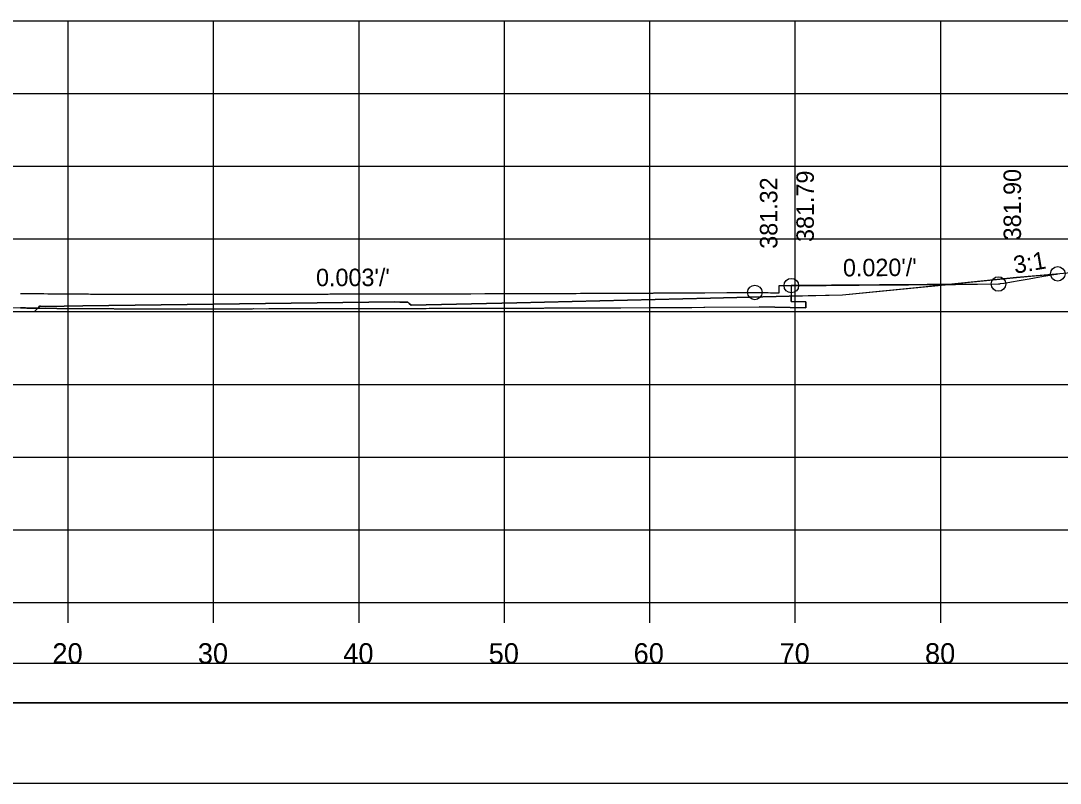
# Model space of a CAD drawing. Extents: x -37291014 to -37290680, y -936053 to -933067.
# Drawn here: x -37290826.4 to -37290754.9, y -934711.7 to -934659.3 of the extents above; entities that cross this region are included whole.
import ezdxf

# ---------------------------------------------------------------- set-up
doc = ezdxf.new("R2010")
doc.units = 0
for name, color, linetype in [('Default', 7, 'Continuous'), ('R_Alt Surface', 7, 'Continuous'), ('R_Axis', 7, 'Continuous'), ('R_Axis Annot', 7, 'Continuous'), ('R_Contours', 7, 'Continuous'), ('R_Exist Surface', 7, 'Continuous'), ('R_Fin Surface', 7, 'Continuous'), ('R_Grid', 7, 'Continuous'), ('R_No Plot', 7, 'Continuous'), ('R_Xsect Elev', 7, 'Continuous'), ('R_Xsect Slope', 7, 'Continuous')]:
    doc.layers.add(name, color=color, linetype=linetype)

msp = doc.modelspace()

# ---------------------------------------------------------------- linework, layer by layer
at = {"layer": 'Default'}
for points in [[(-37290992.311, -934706.202), (-37290693.892, -934706.202), (-37290693.892, -934703.496), (-37290992.311, -934703.496)], [(-37290992.311, -934711.724), (-37290693.892, -934711.724), (-37290693.892, -934706.202), (-37290992.311, -934706.202)]]:
    msp.add_lwpolyline(points, close=True, dxfattribs=at)
at = {"layer": 'R_Alt Surface'}
for points in [[(-37290773.377, -934677.506), (-37290773.377, -934678.599), (-37290772.367, -934678.619), (-37290772.377, -934679.036), (-37290775.582, -934678.972)], [(-37290826.373, -934679.04), (-37290826.283, -934679.042), (-37290826.078, -934679.044), (-37290826.028, -934679.045), (-37290825.955, -934679.046), (-37290825.658, -934679.05), (-37290825.6, -934679.051), (-37290825.591, -934679.051), (-37290825.259, -934679.055), (-37290825.215, -934679.055), (-37290825.062, -934679.057), (-37290824.832, -934679.059), (-37290824.797, -934679.06), (-37290824.773, -934679.06), (-37290824.491, -934679.063), (-37290824.373, -934679.064), (-37290824.346, -934679.064), (-37290823.883, -934679.068), (-37290823.872, -934679.069), (-37290823.858, -934679.069), (-37290823.358, -934679.073), (-37290823.331, -934679.073), (-37290823.203, -934679.074), (-37290822.796, -934679.077), (-37290822.762, -934679.077), (-37290822.479, -934679.079), (-37290822.26, -934679.08), (-37290822.196, -934679.081), (-37290822.147, -934679.081), (-37290821.695, -934679.084), (-37290821.556, -934679.084), (-37290821.483, -934679.085), (-37290820.872, -934679.088), (-37290820.848, -934679.088), (-37290820.766, -934679.088), (-37290820.144, -934679.091), (-37290819.992, -934679.091), (-37290819.931, -934679.092), (-37290819.367, -934679.094), (-37290819.2, -934679.094), (-37290819.157, -934679.094), (-37290818.939, -934679.095), (-37290818.54, -934679.096), (-37290817.864, -934679.098), (-37290817.659, -934679.098), (-37290816.722, -934679.1), (-37290816.7, -934679.1), (-37290815.725, -934679.101), (-37290815.557, -934679.101), (-37290815.414, -934679.1), (-37290815.413, -934679.1), (-37290815.296, -934679.1), (-37290815.24, -934679.1), (-37290815.223, -934679.1), (-37290815.047, -934679.099), (-37290815.016, -934679.099), (-37290814.946, -934679.099), (-37290814.714, -934679.099), (-37290814.603, -934679.099), (-37290814.555, -934679.099), (-37290814.439, -934679.098), (-37290814.323, -934679.098), (-37290814.184, -934679.097), (-37290814.125, -934679.097), (-37290814.072, -934679.097), (-37290813.328, -934679.098), (-37290813.063, -934679.097), (-37290813.056, -934679.097), (-37290812.949, -934679.096), (-37290812.934, -934679.096), (-37290812.779, -934679.096), (-37290812.714, -934679.095), (-37290812.153, -934679.096), (-37290811.918, -934679.095), (-37290811.886, -934679.095), (-37290811.801, -934679.094), (-37290811.601, -934679.094), (-37290811.432, -934679.093), (-37290810.941, -934679.093), (-37290810.882, -934679.093), (-37290810.777, -934679.093), (-37290810.725, -934679.093), (-37290810.563, -934679.092), (-37290810.429, -934679.092), (-37290810.359, -934679.091), (-37290809.495, -934679.092), (-37290809.311, -934679.091), (-37290809.206, -934679.091), (-37290808.971, -934679.09), (-37290808.915, -934679.09), (-37290808.697, -934679.09), (-37290808.616, -934679.089), (-37290808.29, -934679.088), (-37290808.228, -934679.088), (-37290808.218, -934679.088), (-37290807.103, -934679.088), (-37290806.768, -934679.087), (-37290806.723, -934679.086), (-37290806.574, -934679.086), (-37290806.351, -934679.085), (-37290806.279, -934679.085), (-37290806.269, -934679.085), (-37290806.236, -934679.085), (-37290806.213, -934679.085), (-37290805.95, -934679.084), (-37290805.221, -934679.084), (-37290805.117, -934679.083), (-37290805.092, -934679.083), (-37290804.69, -934679.082), (-37290804.364, -934679.082), (-37290804.355, -934679.082), (-37290804.343, -934679.082), (-37290803.985, -934679.081), (-37290803.58, -934679.08), (-37290803.524, -934679.08), (-37290803.503, -934679.08), (-37290803.402, -934679.079), (-37290802.641, -934679.079), (-37290802.338, -934679.078), (-37290802.312, -934679.078), (-37290802.107, -934679.077), (-37290801.951, -934679.076), (-37290801.18, -934679.075), (-37290801.136, -934679.075), (-37290801.103, -934679.075), (-37290800.802, -934679.074), (-37290800.374, -934679.074), (-37290800.284, -934679.073), (-37290800.238, -934679.073), (-37290799.858, -934679.072), (-37290798.898, -934679.07), (-37290798.884, -934679.07), (-37290798.837, -934679.07), (-37290798.484, -934679.069), (-37290798.277, -934679.068), (-37290798.214, -934679.068), (-37290798.132, -934679.068), (-37290798.099, -934679.068), (-37290797.798, -934679.067), (-37290796.535, -934679.064), (-37290796.454, -934679.064), (-37290796.433, -934679.064), (-37290796.328, -934679.064), (-37290796.139, -934679.063), (-37290795.797, -934679.062), (-37290795.493, -934679.061), (-37290795.403, -934679.061), (-37290794.448, -934679.059), (-37290794.07, -934679.057), (-37290794.061, -934679.057), (-37290793.272, -934679.055), (-37290792.915, -934679.054), (-37290792.374, -934679.052), (-37290792.293, -934679.052), (-37290792.276, -934679.052), (-37290791.775, -934679.05), (-37290791.525, -934679.049), (-37290791.431, -934679.049), (-37290791.247, -934679.049), (-37290790.557, -934679.046), (-37290790.404, -934679.046), (-37290790.323, -934679.045), (-37290790.286, -934679.045), (-37290790.022, -934679.044), (-37290789.956, -934679.044), (-37290788.166, -934679.038), (-37290787.878, -934679.037), (-37290787.86, -934679.037), (-37290787.857, -934679.037), (-37290787.004, -934679.033), (-37290786.833, -934679.032), (-37290786.756, -934679.032), (-37290786.476, -934679.031), (-37290786.396, -934679.031), (-37290786.384, -934679.031), (-37290785.5, -934679.027), (-37290785.346, -934679.026), (-37290785.191, -934679.026), (-37290785.106, -934679.025), (-37290783.063, -934679.015), (-37290782.918, -934679.015), (-37290782.887, -934679.015), (-37290782.878, -934679.015), (-37290782.824, -934679.014), (-37290782.813, -934679.014), (-37290782.629, -934679.014), (-37290780.409, -934679.001), (-37290780.377, -934679.001), (-37290780.287, -934679.001), (-37290780.214, -934679.001), (-37290779.401, -934678.996), (-37290779.361, -934678.996), (-37290779.324, -934678.996), (-37290779.317, -934678.996), (-37290775.582, -934678.972)]]:
    msp.add_lwpolyline(points, dxfattribs=at)
at = {"layer": 'R_Axis'}
for p, q in [((-37290993.102, -934699.296), (-37290693.102, -934699.296)), ((-37290823.102, -934700.696), (-37290823.102, -934699.296)), ((-37290813.102, -934700.696), (-37290813.102, -934699.296)), ((-37290803.102, -934700.696), (-37290803.102, -934699.296)), ((-37290793.102, -934700.696), (-37290793.102, -934699.296)), ((-37290783.102, -934700.696), (-37290783.102, -934699.296)), ((-37290773.102, -934700.696), (-37290773.102, -934699.296)), ((-37290763.102, -934700.696), (-37290763.102, -934699.296))]:
    msp.add_line(p, q, dxfattribs=at)
at = {"layer": 'R_Contours'}
msp.add_line((-37290773.377, -934677.506), (-37290773.377, -934678.218), dxfattribs=at)
for points in [[(-37290755.183, -934676.709), (-37290757.888, -934676.958), (-37290762.564, -934677.424)], [(-37290762.564, -934677.424), (-37290762.364, -934677.422), (-37290762.075, -934677.42), (-37290761.796, -934677.418), (-37290760.578, -934677.407), (-37290759.131, -934677.394), (-37290759.035, -934677.378), (-37290758.994, -934677.37), (-37290758.769, -934677.331), (-37290758.745, -934677.327), (-37290758.095, -934677.215), (-37290757.854, -934677.173), (-37290757.018, -934677.03), (-37290756.043, -934676.864), (-37290755.88, -934676.836), (-37290755.183, -934676.718)], [(-37290755.183, -934676.718), (-37290755.183, -934676.709)], [(-37290773.377, -934678.218), (-37290769.863, -934678.151), (-37290762.564, -934677.424)], [(-37290762.564, -934677.424), (-37290763.36, -934677.431), (-37290764.024, -934677.436), (-37290765.308, -934677.446), (-37290765.785, -934677.45), (-37290766.202, -934677.454), (-37290766.23, -934677.454), (-37290766.258, -934677.454), (-37290767.302, -934677.462), (-37290768.716, -934677.473), (-37290768.987, -934677.475), (-37290769.108, -934677.476), (-37290770.606, -934677.487), (-37290770.972, -934677.489), (-37290771.146, -934677.49), (-37290772.081, -934677.497), (-37290772.308, -934677.499), (-37290772.327, -934677.499), (-37290773.377, -934677.506)], [(-37290773.377, -934678.218), (-37290773.528, -934678.221), (-37290778.937, -934678.366), (-37290792.257, -934678.695), (-37290799.508, -934678.849), (-37290799.643, -934678.73), (-37290799.749, -934678.645), (-37290800.07, -934678.644), (-37290800.294, -934678.643), (-37290800.668, -934678.627), (-37290809.532, -934678.742), (-37290822.086, -934678.905), (-37290824.665, -934678.932), (-37290825.008, -934678.927), (-37290825.065, -934678.928), (-37290825.113, -934678.982), (-37290825.186, -934679.056)], [(-37290775.582, -934678.972), (-37290772.377, -934679.036), (-37290772.367, -934678.619), (-37290773.377, -934678.599), (-37290773.377, -934678.218)], [(-37290832.102, -934679.295), (-37290831.45, -934679.298), (-37290825.393, -934679.265), (-37290825.186, -934679.056)], [(-37290825.186, -934679.056), (-37290825.215, -934679.055), (-37290825.259, -934679.055), (-37290825.6, -934679.051), (-37290825.658, -934679.05), (-37290825.955, -934679.046), (-37290826.028, -934679.045), (-37290826.078, -934679.044), (-37290826.283, -934679.042), (-37290826.373, -934679.04), (-37290826.389, -934679.04), (-37290829.102, -934679.105)], [(-37290825.186, -934679.056), (-37290825.062, -934679.057), (-37290824.832, -934679.059), (-37290824.797, -934679.06), (-37290824.773, -934679.06), (-37290824.491, -934679.063), (-37290824.373, -934679.064), (-37290824.346, -934679.064), (-37290823.883, -934679.068), (-37290823.872, -934679.069), (-37290823.858, -934679.069), (-37290823.358, -934679.073), (-37290823.331, -934679.073), (-37290823.203, -934679.074), (-37290822.796, -934679.077), (-37290822.762, -934679.077), (-37290822.479, -934679.079), (-37290822.26, -934679.08), (-37290822.196, -934679.081), (-37290822.147, -934679.081), (-37290821.695, -934679.084), (-37290821.556, -934679.084), (-37290821.483, -934679.085), (-37290820.872, -934679.088), (-37290820.848, -934679.088), (-37290820.766, -934679.088), (-37290820.144, -934679.091), (-37290819.992, -934679.091), (-37290819.931, -934679.092), (-37290819.367, -934679.094), (-37290819.2, -934679.094), (-37290819.157, -934679.094), (-37290818.939, -934679.095), (-37290818.54, -934679.096), (-37290817.864, -934679.098), (-37290817.659, -934679.098), (-37290816.722, -934679.1), (-37290816.7, -934679.1), (-37290815.725, -934679.101), (-37290815.557, -934679.101), (-37290815.414, -934679.1), (-37290815.296, -934679.1), (-37290815.24, -934679.1), (-37290815.223, -934679.1), (-37290815.047, -934679.099), (-37290815.016, -934679.099), (-37290814.946, -934679.099), (-37290814.714, -934679.099), (-37290814.603, -934679.099), (-37290814.555, -934679.099), (-37290814.439, -934679.098), (-37290814.323, -934679.098), (-37290814.184, -934679.097), (-37290814.125, -934679.097), (-37290814.072, -934679.097), (-37290813.328, -934679.098), (-37290813.063, -934679.097), (-37290812.949, -934679.096), (-37290812.934, -934679.096), (-37290812.779, -934679.096), (-37290812.714, -934679.095), (-37290812.153, -934679.096), (-37290811.918, -934679.095), (-37290811.886, -934679.095), (-37290811.801, -934679.094), (-37290811.601, -934679.094), (-37290811.432, -934679.093), (-37290810.941, -934679.093), (-37290810.882, -934679.093), (-37290810.777, -934679.093), (-37290810.725, -934679.093), (-37290810.563, -934679.092), (-37290810.429, -934679.092), (-37290810.359, -934679.091), (-37290809.495, -934679.092), (-37290809.311, -934679.091), (-37290809.206, -934679.091), (-37290808.971, -934679.09), (-37290808.915, -934679.09), (-37290808.697, -934679.09), (-37290808.616, -934679.089), (-37290808.29, -934679.088), (-37290808.228, -934679.088), (-37290807.103, -934679.088), (-37290806.768, -934679.087), (-37290806.723, -934679.086), (-37290806.574, -934679.086), (-37290806.351, -934679.085), (-37290806.279, -934679.085), (-37290806.236, -934679.085), (-37290806.213, -934679.085), (-37290805.95, -934679.084), (-37290805.221, -934679.084), (-37290805.117, -934679.083), (-37290805.092, -934679.083), (-37290804.69, -934679.082), (-37290804.364, -934679.082), (-37290804.343, -934679.082), (-37290803.985, -934679.081), (-37290803.58, -934679.08), (-37290803.524, -934679.08), (-37290803.503, -934679.08), (-37290803.402, -934679.079), (-37290802.641, -934679.079), (-37290802.338, -934679.078), (-37290802.312, -934679.078), (-37290802.107, -934679.077), (-37290801.951, -934679.076), (-37290801.18, -934679.075), (-37290801.136, -934679.075), (-37290801.103, -934679.075), (-37290800.802, -934679.074), (-37290800.374, -934679.074), (-37290800.284, -934679.073), (-37290800.238, -934679.073), (-37290799.858, -934679.072), (-37290798.898, -934679.07), (-37290798.884, -934679.07), (-37290798.837, -934679.07), (-37290798.484, -934679.069), (-37290798.277, -934679.068), (-37290798.214, -934679.068), (-37290798.132, -934679.068), (-37290798.099, -934679.068), (-37290797.798, -934679.067), (-37290796.535, -934679.064), (-37290796.454, -934679.064), (-37290796.433, -934679.064), (-37290796.328, -934679.064), (-37290796.139, -934679.063), (-37290795.797, -934679.062), (-37290795.493, -934679.061), (-37290795.403, -934679.061), (-37290794.448, -934679.059), (-37290794.07, -934679.057), (-37290793.272, -934679.055), (-37290792.915, -934679.054), (-37290792.374, -934679.052), (-37290792.293, -934679.052), (-37290792.276, -934679.052), (-37290791.775, -934679.05), (-37290791.525, -934679.049), (-37290791.431, -934679.049), (-37290791.247, -934679.049), (-37290790.557, -934679.046), (-37290790.404, -934679.046), (-37290790.323, -934679.045), (-37290790.286, -934679.045), (-37290790.022, -934679.044), (-37290789.956, -934679.044), (-37290788.166, -934679.038), (-37290787.878, -934679.037), (-37290787.86, -934679.037), (-37290787.004, -934679.033), (-37290786.833, -934679.032), (-37290786.756, -934679.032), (-37290786.476, -934679.031), (-37290786.396, -934679.031), (-37290786.384, -934679.031), (-37290785.5, -934679.027), (-37290785.346, -934679.026), (-37290785.191, -934679.026), (-37290785.106, -934679.025), (-37290783.063, -934679.015), (-37290782.918, -934679.015), (-37290782.887, -934679.015), (-37290782.824, -934679.014), (-37290782.813, -934679.014), (-37290782.629, -934679.014), (-37290780.409, -934679.001), (-37290780.377, -934679.001), (-37290780.287, -934679.001), (-37290780.214, -934679.001), (-37290779.401, -934678.996), (-37290779.361, -934678.996), (-37290779.324, -934678.996), (-37290775.582, -934678.972)]]:
    msp.add_lwpolyline(points, dxfattribs=at)
at = {"layer": 'R_Exist Surface'}
msp.add_lwpolyline([(-37290831.45, -934679.298), (-37290825.393, -934679.265), (-37290825.113, -934678.982), (-37290825.065, -934678.928), (-37290825.008, -934678.927), (-37290824.665, -934678.932), (-37290822.086, -934678.905), (-37290809.532, -934678.742), (-37290800.668, -934678.627), (-37290800.294, -934678.643), (-37290800.07, -934678.644), (-37290799.749, -934678.645), (-37290799.643, -934678.73), (-37290799.508, -934678.849), (-37290792.257, -934678.695), (-37290778.937, -934678.366), (-37290773.528, -934678.221), (-37290769.863, -934678.151), (-37290757.888, -934676.958), (-37290746.73, -934675.928)], dxfattribs=at)
at = {"layer": 'R_Fin Surface'}
msp.add_lwpolyline([(-37290826.373, -934678.04), (-37290826.284, -934678.041), (-37290826.079, -934678.044), (-37290826.029, -934678.045), (-37290825.956, -934678.046), (-37290825.658, -934678.05), (-37290825.6, -934678.051), (-37290825.591, -934678.051), (-37290825.26, -934678.055), (-37290825.215, -934678.055), (-37290825.063, -934678.057), (-37290824.832, -934678.059), (-37290824.798, -934678.06), (-37290824.774, -934678.06), (-37290824.491, -934678.063), (-37290824.374, -934678.064), (-37290824.347, -934678.064), (-37290823.883, -934678.068), (-37290823.873, -934678.068), (-37290823.859, -934678.069), (-37290823.358, -934678.073), (-37290823.332, -934678.073), (-37290823.203, -934678.074), (-37290822.797, -934678.077), (-37290822.762, -934678.077), (-37290822.479, -934678.079), (-37290822.26, -934678.08), (-37290822.197, -934678.081), (-37290822.147, -934678.081), (-37290821.696, -934678.083), (-37290821.556, -934678.084), (-37290821.483, -934678.085), (-37290820.873, -934678.088), (-37290820.849, -934678.088), (-37290820.767, -934678.088), (-37290820.144, -934678.091), (-37290819.993, -934678.091), (-37290819.932, -934678.092), (-37290819.368, -934678.094), (-37290819.201, -934678.094), (-37290819.158, -934678.094), (-37290818.939, -934678.095), (-37290818.541, -934678.096), (-37290817.865, -934678.098), (-37290817.66, -934678.098), (-37290816.722, -934678.1), (-37290816.701, -934678.1), (-37290815.725, -934678.101), (-37290815.558, -934678.101), (-37290815.415, -934678.1), (-37290815.413, -934678.1), (-37290815.297, -934678.1), (-37290815.241, -934678.1), (-37290815.224, -934678.1), (-37290815.048, -934678.099), (-37290815.017, -934678.099), (-37290814.947, -934678.099), (-37290814.715, -934678.099), (-37290814.604, -934678.098), (-37290814.555, -934678.098), (-37290814.44, -934678.098), (-37290814.324, -934678.098), (-37290814.185, -934678.097), (-37290814.126, -934678.097), (-37290814.073, -934678.097), (-37290813.329, -934678.097), (-37290813.064, -934678.097), (-37290813.056, -934678.096), (-37290812.95, -934678.096), (-37290812.934, -934678.096), (-37290812.78, -934678.095), (-37290812.715, -934678.095), (-37290812.153, -934678.096), (-37290811.919, -934678.095), (-37290811.887, -934678.095), (-37290811.801, -934678.094), (-37290811.602, -934678.094), (-37290811.433, -934678.093), (-37290810.941, -934678.093), (-37290810.882, -934678.093), (-37290810.778, -934678.093), (-37290810.726, -934678.093), (-37290810.564, -934678.092), (-37290810.429, -934678.092), (-37290810.36, -934678.091), (-37290809.495, -934678.092), (-37290809.312, -934678.091), (-37290809.207, -934678.091), (-37290808.972, -934678.09), (-37290808.916, -934678.089), (-37290808.698, -934678.09), (-37290808.616, -934678.089), (-37290808.291, -934678.088), (-37290808.229, -934678.088), (-37290808.219, -934678.088), (-37290807.103, -934678.088), (-37290806.768, -934678.087), (-37290806.724, -934678.086), (-37290806.575, -934678.086), (-37290806.352, -934678.085), (-37290806.279, -934678.085), (-37290806.27, -934678.085), (-37290806.237, -934678.085), (-37290806.214, -934678.085), (-37290805.95, -934678.084), (-37290805.222, -934678.084), (-37290805.117, -934678.083), (-37290805.093, -934678.083), (-37290804.69, -934678.082), (-37290804.364, -934678.082), (-37290804.355, -934678.081), (-37290804.344, -934678.081), (-37290803.986, -934678.081), (-37290803.58, -934678.08), (-37290803.525, -934678.08), (-37290803.504, -934678.08), (-37290803.403, -934678.079), (-37290802.642, -934678.079), (-37290802.338, -934678.078), (-37290802.313, -934678.077), (-37290802.108, -934678.077), (-37290801.952, -934678.076), (-37290801.18, -934678.075), (-37290801.137, -934678.075), (-37290801.103, -934678.075), (-37290800.802, -934678.074), (-37290800.374, -934678.073), (-37290800.285, -934678.073), (-37290800.239, -934678.073), (-37290799.859, -934678.072), (-37290798.899, -934678.07), (-37290798.885, -934678.07), (-37290798.837, -934678.07), (-37290798.484, -934678.069), (-37290798.278, -934678.068), (-37290798.215, -934678.068), (-37290798.132, -934678.068), (-37290798.099, -934678.068), (-37290797.799, -934678.067), (-37290796.536, -934678.064), (-37290796.454, -934678.064), (-37290796.433, -934678.064), (-37290796.328, -934678.064), (-37290796.14, -934678.063), (-37290795.798, -934678.062), (-37290795.494, -934678.061), (-37290795.404, -934678.061), (-37290794.449, -934678.058), (-37290794.07, -934678.057), (-37290794.062, -934678.057), (-37290793.272, -934678.055), (-37290792.916, -934678.054), (-37290792.374, -934678.052), (-37290792.293, -934678.052), (-37290792.276, -934678.052), (-37290791.776, -934678.05), (-37290791.526, -934678.049), (-37290791.432, -934678.049), (-37290791.247, -934678.048), (-37290790.558, -934678.046), (-37290790.405, -934678.046), (-37290790.324, -934678.045), (-37290790.286, -934678.045), (-37290790.023, -934678.044), (-37290789.957, -934678.044), (-37290788.166, -934678.038), (-37290787.879, -934678.037), (-37290787.86, -934678.036), (-37290787.858, -934678.036), (-37290787.005, -934678.033), (-37290786.833, -934678.032), (-37290786.757, -934678.032), (-37290786.477, -934678.031), (-37290786.397, -934678.031), (-37290786.384, -934678.031), (-37290785.5, -934678.027), (-37290785.346, -934678.026), (-37290785.191, -934678.026), (-37290785.106, -934678.025), (-37290783.064, -934678.015), (-37290782.919, -934678.015), (-37290782.888, -934678.015), (-37290782.878, -934678.015), (-37290782.825, -934678.014), (-37290782.814, -934678.014), (-37290782.629, -934678.014), (-37290780.41, -934678.001), (-37290780.377, -934678.001), (-37290780.287, -934678.001), (-37290780.214, -934678.001), (-37290779.401, -934677.996), (-37290779.361, -934677.996), (-37290779.325, -934677.996), (-37290779.318, -934677.996), (-37290777.804, -934677.986), (-37290777.776, -934677.986), (-37290777.773, -934677.986), (-37290777.771, -934677.986), (-37290777.719, -934677.986), (-37290776.119, -934677.975), (-37290776.116, -934677.975), (-37290775.885, -934677.973), (-37290775.127, -934677.986), (-37290774.979, -934677.989), (-37290774.802, -934677.992), (-37290774.22, -934678.002), (-37290774.219, -934677.885), (-37290774.218, -934677.502), (-37290773.736, -934677.504), (-37290773.377, -934677.506), (-37290772.327, -934677.499), (-37290772.308, -934677.499), (-37290772.081, -934677.497), (-37290771.146, -934677.49), (-37290770.972, -934677.489), (-37290770.606, -934677.487), (-37290769.108, -934677.476), (-37290768.987, -934677.475), (-37290768.716, -934677.473), (-37290767.302, -934677.462), (-37290766.258, -934677.454), (-37290766.23, -934677.454), (-37290766.202, -934677.454), (-37290765.785, -934677.45), (-37290765.308, -934677.446), (-37290764.024, -934677.436), (-37290763.36, -934677.431), (-37290762.364, -934677.422), (-37290762.075, -934677.42), (-37290761.796, -934677.418), (-37290760.578, -934677.407), (-37290759.131, -934677.394), (-37290759.035, -934677.378), (-37290758.994, -934677.37), (-37290758.769, -934677.331), (-37290758.745, -934677.327), (-37290758.095, -934677.215), (-37290757.854, -934677.173), (-37290757.018, -934677.03), (-37290756.043, -934676.864), (-37290755.88, -934676.836), (-37290755.183, -934676.718), (-37290755.143, -934676.712), (-37290755.052, -934676.696)], dxfattribs=at)
at = {"layer": 'R_Grid'}
for p, q in [((-37290993.102, -934659.296), (-37290693.102, -934659.296)), ((-37290823.102, -934699.296), (-37290823.102, -934659.296)), ((-37290813.102, -934699.296), (-37290813.102, -934659.296)), ((-37290803.102, -934699.296), (-37290803.102, -934659.296)), ((-37290793.102, -934699.296), (-37290793.102, -934659.296)), ((-37290783.102, -934699.296), (-37290783.102, -934659.296)), ((-37290773.102, -934699.296), (-37290773.102, -934659.296)), ((-37290763.102, -934699.296), (-37290763.102, -934659.296)), ((-37290993.102, -934664.296), (-37290693.102, -934664.296)), ((-37290993.102, -934669.296), (-37290693.102, -934669.296)), ((-37290993.102, -934674.296), (-37290693.102, -934674.296)), ((-37290993.102, -934679.296), (-37290693.102, -934679.296)), ((-37290993.102, -934684.296), (-37290693.102, -934684.296)), ((-37290993.102, -934689.296), (-37290693.102, -934689.296)), ((-37290993.102, -934694.296), (-37290693.102, -934694.296)), ((-37290993.102, -934699.296), (-37290693.102, -934699.296))]:
    msp.add_line(p, q, dxfattribs=at)
at = {"layer": 'R_No Plot'}
for centre in [(-37290755.052, -934676.696), (-37290773.377, -934677.506), (-37290759.131, -934677.394), (-37290775.885, -934677.973)]:
    msp.add_circle(centre, 0.5, dxfattribs=at)

# ---------------------------------------------------------------- texts
at = {"layer": 'R_Axis Annot'}
for s, p in [('20', (-37290824.187, -934703.496)), ('30', (-37290814.187, -934703.496)), ('40', (-37290804.187, -934703.496)), ('50', (-37290794.187, -934703.496)), ('60', (-37290784.221, -934703.496)), ('70', (-37290774.187, -934703.496)), ('80', (-37290764.187, -934703.496))]:
    msp.add_text(s, height=1.4, dxfattribs=at).set_placement(p)
at = {"layer": 'R_Xsect Elev'}
for s, rotation, p in [('381.79', 90, (-37290771.827, -934674.506)), ('381.90', 90, (-37290757.581, -934674.394)), ('381.32', 90, (-37290774.335, -934674.973)), ("0.003'/'", 0.14215, (-37290806.057, -934677.548))]:
    msp.add_text(s, height=1.2, rotation=rotation, dxfattribs=at).set_placement(p)
at = {"layer": 'R_Xsect Slope'}
for s, rotation, p in [("0.020'/'", 0.44865, (-37290769.821, -934676.878)), ('3:1', 9.70941, (-37290757.995, -934676.693))]:
    msp.add_text(s, height=1.2, rotation=rotation, dxfattribs=at).set_placement(p)

doc.saveas('drawing.dxf')
